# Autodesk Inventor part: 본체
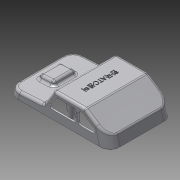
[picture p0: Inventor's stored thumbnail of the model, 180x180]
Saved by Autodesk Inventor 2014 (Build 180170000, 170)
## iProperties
Created: 2015-05
Part Number: 본체
Material: ABS 플라스틱
Document SubType Name: Modeling
Designer: Administrator
Density: 1.06 g/cm^3
Appearance: 매끄러움 - 흰색
Mass: 35.782 g
Surface Area: 333.401 cm^2
Volume: 33.7566 cm^3
Author: Administrator
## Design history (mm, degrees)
sketch "스케치1"
  geometry: L1 (61, 0)-(-61, 0); L2 (-61, 0)-(-61, 30); L3 (-61, 30)-(19, 30); L4 (19, 10.201)-(61, 8); L5 (61, 8)-(61, 0); L6 (19, 30)-(19, 10.201); 2 further points
  constraints: 12 end point, 2 parallel, 2 perpendicular, 1 coincident, 1 horizontal, 1 midpoint
  dimensions: "d0" = 122 distance of L1.end L1.start; "d2" = 30 distance of L1.end L2.end; "d4" = 3 deg angle of L1 L4; "d5" = 8 distance of L4.end L1.start; "d6" = 80 distance of L2.end L3.end
extrude "돌출1" new body sketch "스케치1" stored distance "d7" = 76; taper "d8" = 0 deg
sketch "스케치2"
  geometry: L1 (61, 0)-(61, 30) reference; L2 (61, 30)-(-19, 30) reference; L3 (31, 30)-(61, 10); 1 further point
  constraints: 2 end point, 2 point on line
  dimensions: "d9" = 20 vertical distance of L3.start L3.end; "d10" = 30 horizontal distance of L3.start L3.end
extrude "돌출2" cut sketch "스케치2" stored distance "d11" = 76; taper "d12" = 0 deg
sketch "스케치3"
  geometry: L1 (61, 10)-(31, 30) reference; L2 (-61, 0)-(61, 0) reference; L3 (61, 0)-(61, 10) reference; L4 (57.738, 12.175)-(61, 0); 1 further point
  constraints: 2 end point, 1 point on line
  dimensions: "d13" = 105 deg angle of L2 L4
extrude "돌출3" cut sketch "스케치3" stored distance "d14" = 76; taper "d15" = 0 deg
sketch "스케치4"
  geometry: L1 (31, 30)-(-19, 30) reference; L2 (-19, 30)-(-19, 10.201) reference; L3 (-19, 10.201)-(-61, 8) reference; L4 (-19, 10.201)-(-6.628, 30); 1 further point
  constraints: 2 end point, 1 point on line
  dimensions: "d16" = 125 deg angle of L3 L4
extrude "돌출4" cut sketch "스케치4" stored distance "d17" = 76; taper "d18" = 0 deg
sketch "스케치5"
  geometry: L1 (-19, 10.201)-(-61, 8) reference; L2 (-50, 8.576)-(-48.471, 13.576); L3 (-48.471, 13.576)-(-32.122, 14.625); L4 (-32.122, 14.625)-(-30, 9.625); 1 further point
  constraints: 6 end point, 2 point on line
  dimensions: "d19" = 70 deg angle of L1 L4; "d20" = 70 deg angle of L1 L2; "d21" = 20 horizontal distance of L4.end L2.start; "d22" = 5 vertical distance of L2.start L2.end; "d23" = 5 vertical distance of L3.end L4.end; "d24" = 11 horizontal distance of L1.end L2.start
extrude "돌출5" join sketch "스케치5" distance "d25" = 76; taper "d26" = 0 deg
sketch "스케치6"
  geometry: L1 (-30, 9.625)-(-32.122, 14.625) reference; L2 (-32.122, 14.625)-(-48.471, 13.576) reference; L3 (-48.471, 13.576)-(-50, 8.576) reference; L4 (-50, 8.576)-(-61, 8) reference; L5 (-50, 8.576)-(-30, 9.625); 1 further point
  constraints: 2 end point, 1 collinear
extrude "돌출6" cut sketch "스케치6" distance "d27" = 25; taper "d28" = 0 deg
sketch "스케치7"
  geometry: L1 (-19, 10.201)-(-61, 8) reference; L2 (-61, 8)-(-61, 0) reference; L3 (-61, 0)-(61, 0) reference; L4 (-61, 0)-(-58.826, 8.114); 1 further point
  constraints: 2 end point, 1 point on line
  dimensions: "d29" = 105 deg angle of L3 L4
extrude "돌출7" cut sketch "스케치7" stored distance "d30" = 25; taper "d31" = 0 deg
fillet "모깎기1" dims "d32" = 12
fillet "모깎기2" dims "d33" = 3
fillet "모깎기3" dims "d34" = 3
fillet "모깎기4" dims "d35" = 3
feature "쉘1" dims "d36" = 2
sketch "스케치8"
  geometry: L1 (-7.51, 28.59)-(-18.172, 11.526) reference; L2 (30.092, 30)-(-4.965, 30) reference; L3 (45.453, 20.365)-(31.756, 29.496) reference; L4 (-4.738, 23.59)-(-10.362, 14.59); L5 (-7.818, 10)-(17.77, 10); L6 (20.77, 13)-(20.77, 22); L7 (17.77, 25)-(-2.194, 25); L8 (22.669, 22)-(22.669, 13); L9 (25.669, 10)-(40.761, 10); L10 (25.669, 25)-(27.261, 25); L11 (28.925, 24.496)-(42.425, 15.496); A1 r 3 centre (-2.194, 22) between (-2.194, 25) and (-4.738, 23.59); A2 r 3 centre (-7.818, 13) between (-10.362, 14.59) and (-7.818, 10); A3 r 3 centre (17.77, 13) between (17.77, 10) and (20.77, 13); A4 r 3 centre (17.77, 22) between (20.77, 22) and (17.77, 25); A5 r 3 centre (25.669, 22) between (25.669, 25) and (22.669, 22); A6 r 3 centre (25.669, 13) between (22.669, 13) and (25.669, 10); A7 r 3 centre (40.761, 13) between (40.761, 10) and (42.425, 15.496); A8 r 3 centre (27.261, 22) between (28.925, 24.496) and (27.261, 25); 7 further points
  constraints: 16 end point, 16 point on circle, 16 tangent, 12 point on line, 8 centre point, 6 equal radius, 4 parallel, 3 perpendicular
  dimensions: "d37" = 5 distance between parallel lines of L4 L1; "d38" = 5 distance between parallel lines of L2 L7; "d39" = 34 distance of point (-13.23, 10) point (20.77, 10); "d40" = 15 distance of point (20.77, 10) point (20.77, 25); "d41" = 3 radius of A1; "d44" = 15 distance of point (22.669, 25) point (22.669, 10); "d45" = 28 distance of point (22.669, 10) point (50.669, 10); "d46" = 5.73038 distance between parallel lines of L3 L11; "d47" = 5 distance between parallel lines of L2 L10; "d48" = 3 radius of A5
extrude "돌출8" cut sketch "스케치8" stored distance "d49" = 25; taper "d50" = 0 deg
node "작업 평면1"
sketch "스케치9"
  geometry: L1 (-23, 0)-(-19, 0); L2 (-12, 0)-(-8, 0); L3 (8, 0)-(12, 0); L4 (19, 0)-(23, 0); A1 r 2 centre (-10, 0) between (-8, 0) and (-12, 0); A2 r 2 centre (-21, 0) between (-19, 0) and (-23, 0); A3 r 2 centre (10, 0) between (12, 0) and (8, 0); A4 r 2 centre (21, 0) between (23, 0) and (19, 0); A5 r 2 centre (-21, 0) between (-23, 0) and (-19, 0); A6 r 2 centre (-10, 0) between (-12, 0) and (-8, 0); A7 r 2 centre (10, 0) between (8, 0) and (12, 0); A8 r 2 centre (21, 0) between (19, 0) and (23, 0); 5 further points
  constraints: 16 point on circle, 8 centre point, 8 end point, 4 coincident, 4 horizontal alignment, 4 midpoint, 3 collinear, 1 horizontal
  dimensions: "d52" = 4 diameter of A3; "d53" = 4 diameter of A4; "d54" = 4 diameter of A1; "d55" = 4 diameter of A2; "d56" = 10 distance of A3.centre point (0, 0); "d57" = 20 distance of A3.centre A1.centre; "d58" = 11 distance of A4.centre A3.centre; "d59" = 11 distance of A1.centre A2.centre
extrude "돌출9" join sketch "스케치9" stored distance "d60" = 25; taper "d61" = 0 deg
chamfer "모따기1" distance "d62" = 1; stored, may be unused: second distance "d63" = 2, angle "d64" = 45 deg
sketch "스케치10"
  geometry: L1 (0, 0)-(97.153, 0) reference; L2 (-10.353, -64)-(-10.353, -12) reference; L3 (0, -2)-(97.153, -2) reference; L4 (107.506, -12)-(107.506, -64) reference; L5 (97.153, -74)-(0, -74) reference; L6 (97.153, -1)-(0, -1); L7 (-11.353, -12)-(-11.353, -64); L8 (0, -75)-(97.153, -75); L9 (108.506, -64)-(108.506, -12); 5 further points; 4 other entities
  constraints: 8 end point, 7 parallel, 16 other
  dimensions: "d65" = 1 distance between parallel lines of L1 L6
extrude "돌출10" join sketch "스케치10" distance "d66" = 1; taper "d67" = 0 deg
sketch "스케치11"
  geometry: L1 (-12.423, -12)-(-12.423, -64) reference; C1 r 3 at (88.577, -38); C2 r 3 at (48.577, -16); C3 r 3 at (48.577, -60); C4 r 3 at (8.577, -38); 1 further point
  constraints: 4 centre point, 2 horizontal alignment, 2 vertical alignment
  dimensions: "d68" = 6 diameter of C1; "d69" = 6 diameter of C3; "d70" = 6 diameter of C2; "d71" = 6 diameter of C4; "d91" = 40 distance of C1.centre point (48.577, -38); "d92" = 40 distance of C4.centre point (48.577, -38); "d93" = 21 distance from line of C4.centre L1 (derived); "d94" = 22 distance of C3.centre point (48.577, -38); "d95" = 44 distance of C3.centre C2.centre
extrude "돌출11" join sketch "스케치11" stored distance "d72" = 1; taper "d73" = 4 deg
node "작업 평면2"
sketch "스케치12"
  geometry: L1 (-5, 23)-(5, 23); L2 (5, 23)-(5, 21); L3 (5, 21)-(-5, 21); L4 (-5, 21)-(-5, 23); L5 (-5, 23)-(5, 21); L6 (5, 23)-(-5, 21); L7 (44.982, 1)-(34.982, 1); L8 (34.982, 1)-(34.982, -1); L9 (34.982, -1)-(44.982, -1); L10 (44.982, -1)-(44.982, 1); L11 (44.982, 1)-(34.982, -1); L12 (34.982, 1)-(44.982, -1); L13 (-5, -21)-(5, -21); L14 (5, -21)-(5, -23); L15 (5, -23)-(-5, -23); L16 (-5, -23)-(-5, -21); L17 (-5, -21)-(5, -23); L18 (5, -21)-(-5, -23); L19 (-44.786, 1)-(-34.786, 1); L20 (-34.786, 1)-(-34.786, -1); L21 (-34.786, -1)-(-44.786, -1); L22 (-44.786, -1)-(-44.786, 1); L23 (-44.786, 1)-(-34.786, -1); L24 (-34.786, 1)-(-44.786, -1); C1 r 3 at (0, 22) reference; C2 r 3 at (40, 0) reference; C3 r 3 at (0, -22) reference; C4 r 3 at (-40, 0) reference; A1 r 5.028 centre (0, 22) between (4.965, 22.79) and (4.965, 21.21) reference; A2 r 5.028 centre (0, -22) between (4.965, -21.21) and (4.965, -22.79) reference; 3 further points; 2 other entities
  constraints: 48 end point, 8 midpoint, 8 parallel, 4 horizontal, 4 perpendicular, 2 vertical alignment, 2 other
  dimensions: "d75" = 10 distance of L2.end L3.end; "d76" = 2 distance of L1.end L2.end; "d77" = 10 distance of L8.end L9.end; "d78" = 2 distance of L7.end L8.end; "d79" = 10 distance of L14.end L15.end; "d80" = 2 distance of L13.end L14.end; "d81" = 10 distance of L20.end L21.end; "d82" = 2 distance of L19.end L20.end
extrude "돌출12" join sketch "스케치12" stored distance "d83" = 1; taper "d84" = 2.5 deg
sketch "스케치13"
  geometry: L1 (0, 0)-(-1.095, 25.103) reference; L2 (-11.476, 7.847)-(-0.813, 24.895) reference; L3 (0, 0)-(-3.694, 20.948); L4 (-4.589, 26.025)-(0.035, 26.025); L5 (-1.095, 25.103)-(-3.694, 20.948); L6 (-3.694, 20.948)-(-4.589, 26.025); 5 further points; 1 other entity
  constraints: 8 end point, 2 horizontal, 2 point on line, 1 coincident, 1 parallel, 1 other
  dimensions: "d85" = 100 deg angle of L3 L4
extrude "돌출13" join sketch "스케치13" stored distance "d86" = 1; taper "d87" = 0 deg
sketch "스케치14"
  geometry: L1 (1.95, 0)-(3.085, 26.025) reference; L2 (-8.015, 25.365)-(27.042, 25.365) reference; L3 (1.95, 0)-(6.539, 26.025); L4 (3.085, 26.025)-(6.539, 26.025); 1 further point
  constraints: 4 end point, 1 parallel
  dimensions: "d88" = 100 deg angle of L4 L3
extrude "돌출14" join sketch "스케치14" stored distance "d89" = 1; taper "d90" = 0 deg
sketch "스케치16"
  geometry: L1 (2.432, -15.957)-(0.983, -16.923) reference; L2 (1.736, 0)-(2.432, -15.957) reference; L3 (1.736, 0)-(0, 0) reference; L4 (1.736, 0)-(4.55, -15.957); L5 (2.432, -15.957)-(4.55, -15.957); L6 (2.432, -15.957)-(4.327, -14.692); 3 further points
  constraints: 6 end point, 2 coincident, 1 collinear, 1 parallel, 1 point on line
  dimensions: "d99" = 100 deg angle of L5 L4
extrude "돌출16" join sketch "스케치16" stored distance "d100" = 1; taper "d101" = 0 deg
sketch "스케치17"
  geometry: L1 (1.354, -9.892)-(-0.427, -9.778) reference; L2 (0, 0)-(-0.427, -9.778) reference; L3 (0, 0)-(-2.349, -9.655); L4 (-0.427, -9.778)-(-2.349, -9.655); 1 further point
  constraints: 4 end point, 1 collinear
  dimensions: "d102" = 100 deg angle of L3 L4
extrude "돌출17" join sketch "스케치17" stored distance "d103" = 1; taper "d104" = 0 deg
sketch "스케치18"
  geometry: L1 (2.425, -10.476)-(0.606, -10.36) reference; L2 (1.968, 0)-(2.425, -10.476) reference; L3 (1.968, 0)-(3.134, -10.522); L4 (2.425, -10.476)-(3.134, -10.522); 1 further point
  constraints: 4 end point, 1 collinear
  dimensions: "d105" = 100 deg angle of L4 L3
extrude "돌출18" join sketch "스케치18" stored distance "d106" = 1; taper "d107" = 0 deg
sketch "스케치20"
  geometry: L1 (-1.038, 23.787)-(0.861, 22.52) reference; L2 (0, 0)-(-1.038, 23.787) reference; L3 (0, 0)-(2.164, 0) reference; L4 (0, 0)-(-4.584, 25.995); L5 (-1.038, 23.787)-(-4.347, 25.995); L6 (-4.347, 25.995)-(-4.584, 25.995); 1 further point
  constraints: 6 end point, 1 collinear, 1 parallel
  dimensions: "d108" = 100 deg angle of L4 L6
extrude "돌출19" join sketch "스케치20" stored distance "d109" = 1; taper "d110" = 0 deg
sketch "스케치21"
  geometry: L1 (3.116, 10.48)-(1.974, 0.145) reference; L2 (1.974, 0.145)-(3.796, 10.48); L3 (3.116, 10.48)-(3.796, 10.48); 3 further points; 1 other entity
  constraints: 4 end point, 1 horizontal, 1 other
  dimensions: "d111" = 100 deg angle of L3 L2
extrude "돌출20" join sketch "스케치21" stored distance "d112" = 1; taper "d113" = 0 deg
sketch "스케치22"
  geometry: C1 r 3 at (0, 0) reference; C2 r 3 at (0, 44) reference; C3 r 3 at (40, 22) reference; C4 r 3 at (-40, 22) reference; 5 further points
  constraints: 4 coincident
hole "구멍1" sketch "스케치22" at (0, 44), (40, 22), (0, 0), (-40, 22) diameter "d114" = 3.242; stored, may be unused: countersink angle "d118" = 90 deg, drill point angle "d120" = 118 deg; dims "d115" = 9, "d116" = 19.05, "d117" = 4.775, "d119" = 11
sketch "스케치23"
  geometry: L1 (65.965, 61)-(65.965, 9) reference; 2 further points
  constraints: 1 horizontal alignment, 1 other
  dimensions: "d121" = 50 distance from line of L1 point (15.965, 35)
feature "엠보싱1" sketch "스케치23" dims "d122" = 0.5, "d123" = 0
node "솔리드1"
mirror "대칭1"
mirror "대칭2"
node "투영된 루프1"
node "투영된 루프2"
node "투영된 루프3"
node "투영된 루프4"
node "투영된 루프6"
node "투영된 루프7"
node "투영된 루프8"
other parameters: "d51" = -63, "d74" = 2
